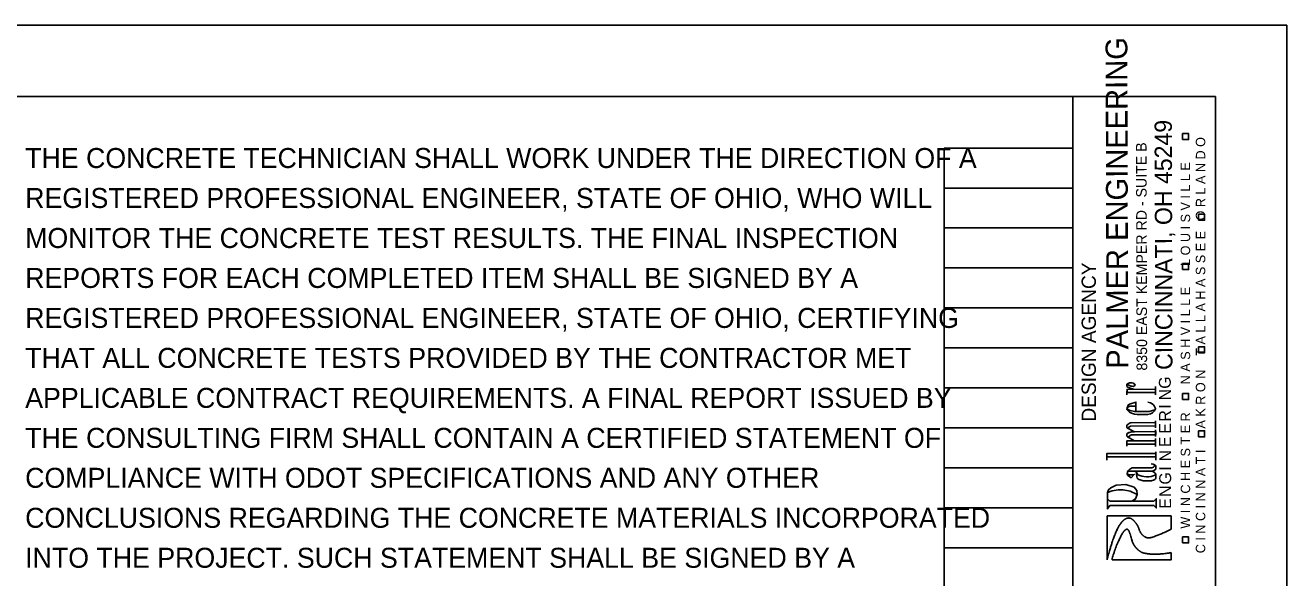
# Model space of a CAD drawing. Extents: x -14.8 to 34, y 0 to 43.2.
# Drawn here: x 25.16 to 34, y 18.13 to 22 of the extents above; entities that cross this region are included whole.
import ezdxf

# ---------------------------------------------------------------- set-up
doc = ezdxf.new("R2010")
doc.units = 0
for name, color, linetype in [('SH_Border', 7, 'Continuous'), ('SH_Cut_Line', 7, 'Continuous'), ('SH_Data', 7, 'Continuous'), ('SH_Text', 7, 'Continuous')]:
    doc.layers.add(name, color=color, linetype=linetype)

msp = doc.modelspace()

# ---------------------------------------------------------------- linework, layer by layer
at = {"layer": 'SH_Border'}
msp.add_line((32.5, 0.5), (32.5, 21.5), dxfattribs=at)
msp.add_lwpolyline([(2, 21.5), (33.5, 21.5), (33.5, 0.5), (2, 0.5)], close=True, dxfattribs=at)
at = {"layer": 'SH_Cut_Line'}
msp.add_lwpolyline([(0, 22), (34, 22), (34, 0), (0, 0)], close=True, dxfattribs=at)
at = {"layer": 'SH_Data'}
for p, q in [((31.6, 0.98), (31.6, 21.14)), ((31.6, 21.14), (32.5, 21.14)), ((32.5, 0.98), (32.5, 21.14)), ((31.6, 20.86), (32.5, 20.86)), ((31.6, 20.58), (32.5, 20.58)), ((31.6, 20.3), (32.5, 20.3)), ((31.6, 20.02), (32.5, 20.02)), ((31.6, 19.74), (32.5, 19.74)), ((32.9208, 19.773), (32.9208, 19.773)), ((33.2542, 19.7731), (33.2542, 19.7731)), ((31.6, 19.46), (32.5, 19.46)), ((31.6, 19.18), (32.5, 19.18)), ((31.6, 18.9), (32.5, 18.9)), ((31.6, 18.62), (32.5, 18.62)), ((31.6, 18.34), (32.5, 18.34))]:
    msp.add_line(p, q, dxfattribs=at)
at = {"layer": 'SH_Text'}
for p, q in [((32.741, 18.5628), (32.741, 18.2567)), ((33.1908, 18.5628), (32.741, 18.5628)), ((33.1908, 18.47), (33.1908, 18.5628)), ((32.741, 18.2567), (32.741, 18.2567)), ((32.7758, 18.2567), (32.7758, 18.2567))]:
    msp.add_line(p, q, dxfattribs=at)
for points in [[(33.2695, 21.1988), (33.3123, 21.1988), (33.3123, 21.2417), (33.2704, 21.2408)], [(33.3808, 20.6337), (33.4236, 20.6337), (33.4236, 20.6765), (33.3817, 20.6756)], [(33.2695, 20.2887), (33.3123, 20.2887), (33.3123, 20.3316), (33.2704, 20.3307)], [(33.3808, 19.7055), (33.4236, 19.7055), (33.4236, 19.7484), (33.3817, 19.7475)], [(32.8803, 19.4854), (32.8981, 19.4952), (32.916, 19.4952), (32.9249, 19.4934), (32.9383, 19.48), (32.9383, 19.4782), (32.9249, 19.4702), (32.916, 19.4711), (32.907, 19.4729)], [(32.8803, 19.4274), (32.8812, 19.4497), (33.0802, 19.4506), (33.0802, 19.4283)], [(32.9427, 19.331), (32.9026, 19.331), (32.8874, 19.3274), (32.8829, 19.3229), (32.8829, 19.3203), (32.882, 19.3158), (32.8838, 19.3113), (32.8856, 19.3087), (32.9026, 19.3015), (32.9338, 19.2944), (33.0355, 19.2944), (33.0766, 19.3069), (33.0721, 19.2988), (33.0587, 19.2855), (33.0463, 19.2792), (33.0275, 19.2739), (32.9517, 19.2739), (32.9338, 19.2765), (32.9115, 19.2819), (32.899, 19.289), (32.8803, 19.3087), (32.8812, 19.3212), (32.8892, 19.339), (32.8981, 19.3461), (32.9427, 19.3604)], [(33.2695, 19.3783), (33.3123, 19.3783), (33.3123, 19.4211), (33.2704, 19.4202)], [(32.8883, 19.1757), (32.882, 19.181), (32.8794, 19.1828), (32.8794, 19.198), (32.8883, 19.206), (32.9026, 19.2141), (32.9106, 19.2159), (33.0811, 19.2167), (33.0811, 19.1944), (32.9061, 19.1918), (32.8972, 19.1882), (32.8936, 19.1855)], [(32.8883, 19.1141), (32.8847, 19.1177), (32.8794, 19.1221), (32.8794, 19.1373), (32.891, 19.1462), (32.9115, 19.1525), (32.9329, 19.1525), (33.082, 19.1534), (33.082, 19.1302), (32.9115, 19.1302), (32.9017, 19.1266)], [(33.3808, 19.1164), (33.4236, 19.1164), (33.4236, 19.1592), (33.3817, 19.1583)], [(32.8803, 19.0659), (32.8803, 19.0882), (33.0811, 19.0891), (33.0811, 19.0659)], [(32.7384, 18.9776), (32.7384, 18.9999), (33.082, 18.9999), (33.082, 18.9767)], [(33.0507, 18.9285), (33.0641, 18.9258), (33.073, 18.9204), (33.073, 18.9124), (33.0659, 18.9044), (33.0552, 18.8999), (32.9177, 18.8999), (32.8999, 18.891), (32.8954, 18.887), (32.8927, 18.8847), (32.8829, 18.8714), (32.882, 18.8571), (32.8874, 18.8473), (32.8919, 18.8428), (32.9088, 18.8303), (32.9311, 18.8535), (32.9222, 18.8508), (32.8954, 18.8499), (32.8874, 18.8535), (32.8838, 18.8598), (32.8838, 18.8705), (32.887, 18.8772), (32.8865, 18.8767), (33.0596, 18.8767), (33.0766, 18.866), (33.082, 18.8571), (33.0757, 18.8482), (33.0641, 18.8428), (33.0489, 18.8383), (33.0329, 18.8366), (33.0177, 18.8366), (32.999, 18.8383), (32.9838, 18.841), (32.9704, 18.8455), (32.9637, 18.8486), (32.957, 18.8517), (32.9508, 18.8589), (32.9445, 18.8767), (32.949, 18.8374), (32.9517, 18.8285), (32.9561, 18.8241), (32.9641, 18.8187), (32.9717, 18.816), (32.9793, 18.8134), (32.9865, 18.8116), (32.9936, 18.8098), (33.0012, 18.8089), (33.0088, 18.808), (33.048, 18.808), (33.0529, 18.8098), (33.0579, 18.8116), (33.0659, 18.8134), (33.0748, 18.8187), (33.0802, 18.8232), (33.082, 18.8285), (33.082, 18.8571), (33.0766, 18.866), (33.0596, 18.8767), (33.073, 18.883), (33.082, 18.891), (33.082, 18.9142), (33.073, 18.9204), (33.0641, 18.9258)], [(32.7428, 18.6839), (32.7428, 18.6125), (32.7607, 18.6366), (33.0686, 18.6366), (33.0855, 18.6197), (33.0855, 18.6839), (33.0677, 18.667), (32.9213, 18.667), (32.9392, 18.6822), (32.9517, 18.7143), (32.9499, 18.742), (32.9302, 18.7643), (32.8722, 18.7839), (32.8053, 18.7785), (32.7678, 18.7607), (32.7517, 18.7464), (32.7428, 18.7268), (32.7758, 18.7393), (32.8187, 18.7455), (32.8535, 18.7464), (32.9035, 18.7375), (32.9517, 18.7143), (32.9392, 18.6822), (32.9151, 18.667), (32.7607, 18.667), (32.7428, 18.6839), (32.7428, 18.7268)], [(33.2695, 18.3737), (33.3123, 18.3737), (33.3123, 18.4166), (33.2704, 18.4157)]]:
    msp.add_lwpolyline(points, close=True, dxfattribs=at)
for points in [[(32.9249, 19.4506), (32.9026, 19.4586), (32.8856, 19.4657), (32.8803, 19.4702), (32.8803, 19.4854), (32.8981, 19.4952), (32.916, 19.4952), (32.9249, 19.4934), (32.9338, 19.4854), (32.9383, 19.48), (32.9383, 19.4782), (32.9249, 19.4702), (32.916, 19.4711), (32.907, 19.4729), (32.8803, 19.4854)], [(32.8803, 19.4104), (32.8812, 19.4497), (33.0802, 19.4506)], [(33.0802, 19.4104), (33.0802, 19.4702)], [(32.9427, 19.2935), (32.9427, 19.3604), (32.8981, 19.3461), (32.8892, 19.339), (32.8847, 19.3256), (32.8812, 19.3212), (32.8803, 19.3087), (32.899, 19.289), (32.9115, 19.2819), (32.9338, 19.2765), (32.9517, 19.2739), (33.0275, 19.2739), (33.0463, 19.2792), (33.0587, 19.2855), (33.0721, 19.2988), (33.0811, 19.3167), (33.0766, 19.3256), (33.0712, 19.3337), (33.0632, 19.3444), (33.0454, 19.356), (33.0275, 19.3604)], [(32.9427, 19.331), (32.9026, 19.331), (32.8901, 19.3283), (32.8847, 19.3256)], [(32.9338, 19.0882), (32.8847, 19.1177), (32.8794, 19.1221), (32.8794, 19.1373), (32.8883, 19.1445), (32.8936, 19.148), (32.9115, 19.1525), (32.9329, 19.1525), (32.8847, 19.1784), (32.8794, 19.1828), (32.8794, 19.198), (32.8883, 19.206), (32.9026, 19.2141), (32.9106, 19.2159), (33.0811, 19.2167)], [(33.0811, 19.181), (33.0811, 19.2301)], [(33.0811, 19.1195), (33.0811, 19.165)], [(33.0811, 19.0499), (33.0811, 19.1043)], [(32.8803, 19.0507), (32.8803, 19.0882), (33.0811, 19.0891)], [(33.082, 18.9544), (33.082, 19.0115)], [(32.7384, 18.9526), (32.7384, 18.9999), (33.082, 18.9999)], [(32.7758, 18.2567), (33.1908, 18.2567), (33.1908, 18.3058)]]:
    msp.add_lwpolyline(points, dxfattribs=at)
for centre, major_axis, ratio, start_param, end_param in [((33.2642, 18.3025), (-0.4905, 0), 0.87846, 5.855193, 5.894118), ((33.0097, 18.4045), (-0.2108, 0), 0.87846, 5.795806, 5.855193), ((33.0658, 18.3784), (-0.2743, 0), 0.87846, 5.749826, 5.795806), ((33.1077, 18.3566), (-0.3229, 0), 0.87846, 5.707452, 5.749826), ((33.2256, 18.2894), (-0.4635, 0), 0.87846, 5.692164, 5.707452), ((32.8595, 18.5052), (-0.0226, 0), 0.87846, 5.62293, 5.692164), ((32.86, 18.5049), (-0.0233, 0), 0.87846, 5.530169, 5.62293), ((32.8297, 18.5301), (-0.0186, 0), 0.87846, 2.376805, 2.493109), ((32.7929, 18.5546), (-0.0647, 0), 0.87846, 2.493108, 2.531888), ((32.8891, 18.4958), (-0.0525, 0), 0.87846, 5.630169, 5.678013), ((32.9316, 18.4673), (-0.106, 0), 0.87846, 5.621033, 5.63017), ((33.5343, 18.0545), (-0.8702, 0), 0.87846, 5.617844, 5.621032), ((32.9292, 18.4716), (-0.101, 0), 0.87846, 5.581326, 5.617844), ((32.958, 18.4503), (-0.1387, 0), 0.87846, 5.55016, 5.581326), ((32.8723, 18.518), (-0.0234, 0), 0.87846, 5.403561, 5.55016), ((32.9933, 18.3895), (-0.2133, 0), 0.87846, 5.35501, 5.403561), ((32.9271, 18.4673), (-0.1027, 0), 0.87846, 5.295141, 5.35501), ((32.9077, 18.4931), (-0.0675, 0), 0.87846, 5.221294, 5.295141), ((32.8871, 18.5255), (-0.0253, 0), 0.87846, 5.021813, 5.221294), ((32.8954, 18.5027), (-0.0525, 0), 0.87846, 4.883334, 5.021813), ((32.8945, 18.5076), (-0.0469, 0), 0.87846, 4.755052, 4.883334), ((32.8934, 18.5286), (-0.023, 0), 0.87846, 4.571575, 4.755052), ((32.8907, 18.5115), (-0.0426, 0), 0.87846, 4.449144, 4.571575), ((32.8967, 18.531), (-0.0196, 0), 0.87846, 4.268543, 4.449144), ((32.8633, 18.4693), (-0.0974, 0), 0.87846, 4.241427, 4.268543), ((32.8979, 18.5291), (-0.021, 0), 0.87846, 4.183087, 4.241427), ((32.8758, 18.4959), (-0.0647, 0), 0.87846, 4.138734, 4.183087), ((32.8855, 18.5091), (-0.0469, 0), 0.87846, 4.086609, 4.138734), ((32.8832, 18.5062), (-0.0509, 0), 0.87846, 4.024354, 4.086609), ((32.8849, 18.5081), (-0.0481, 0), 0.87846, 3.960321, 4.024354), ((32.8482, 18.4737), (-0.1019, 0), 0.87846, 3.920059, 3.960321), ((32.7808, 18.4153), (-0.1965, 0), 0.87846, 3.891072, 3.920059), ((32.6774, 18.3307), (-0.3379, 0), 0.87846, 3.874263, 3.891072), ((32.8217, 18.4447), (-0.1437, 0), 0.87846, 3.848492, 3.874263), ((32.8307, 18.4515), (-0.1318, 0), 0.87846, 3.81119, 3.848492), ((32.7814, 18.4172), (-0.1947, 0), 0.87846, 3.780496, 3.811191), ((32.7693, 18.4094), (-0.2098, 0), 0.87846, 3.754086, 3.780496), ((32.8146, 18.4373), (-0.1544, 0), 0.87846, 3.723306, 3.754086), ((32.7885, 18.4222), (-0.1857, 0), 0.87846, 3.696658, 3.723306), ((32.8051, 18.4313), (-0.1662, 0), 0.87846, 3.66849, 3.696658), ((32.78, 18.4184), (-0.1952, 0), 0.87846, 3.643808, 3.66849), ((32.8348, 18.4449), (-0.1326, 0), 0.87846, 3.613866, 3.643809), ((32.8635, 18.4578), (-0.1004, 0), 0.87846, 3.588674, 3.613866), ((32.7958, 18.4292), (-0.1755, 0), 0.87846, 3.569621, 3.588674), ((32.847, 18.4498), (-0.1192, 0), 0.87846, 3.522125, 3.569621), ((32.7863, 18.4284), (-0.1846, 0), 0.87846, 3.483955, 3.522125), ((32.8049, 18.4342), (-0.1649, 0), 0.87846, 3.442005, 3.483955), ((33.33, 18.5772), (-0.3849, 0), 0.87846, 0.300413, 0.327872), ((33.2036, 18.2843), (-0.4404, 0), 0.87846, 5.967993, 6.015499), ((34.0259, 18.0488), (-1.3053, 0), 0.87846, 5.940399, 5.967993), ((33.5753, 18.1901), (-0.8269, 0), 0.87846, 5.917138, 5.940399), ((33.5917, 18.1846), (-0.8444, 0), 0.87846, 5.894118, 5.917138), ((32.3944, 18.5495), (-0.4655, 0), 0.87846, 2.717844, 2.740099), ((32.0455, 18.6796), (-0.8445, 0), 0.87846, 2.740099, 2.758854), ((33.8353, 18.0445), (-1.0858, 0), 0.87846, 5.883775, 5.898363), ((33.3213, 18.2351), (-0.5279, 0), 0.87846, 5.860363, 5.883775), ((33.5257, 18.1543), (-0.752, 0), 0.87846, 5.840747, 5.860363), ((33.0115, 18.3683), (-0.183, 0), 0.87846, 5.783384, 5.840747), ((32.9209, 18.4117), (-0.0798, 0), 0.87846, 5.696475, 5.783384), ((32.9155, 18.4149), (-0.0732, 0), 0.87846, 5.643254, 5.696475), ((32.9804, 18.3725), (-0.1542, 0), 0.87846, 5.60658, 5.643254), ((32.9543, 18.3909), (-0.1206, 0), 0.87846, 5.557186, 5.60658), ((32.8887, 18.4421), (-0.0329, 0), 0.87846, 5.462631, 5.557186), ((32.8786, 18.4516), (-0.0181, 0), 0.87846, 5.357779, 5.462631), ((32.9369, 18.3836), (-0.115, 0), 0.87846, 5.31618, 5.357779), ((32.9007, 18.4297), (-0.0513, 0), 0.87846, 5.228087, 5.31618), ((32.8836, 18.4561), (-0.0167, 0), 0.87846, 5.073461, 5.228087), ((32.8804, 18.4635), (-0.0077, 0), 0.87846, 4.821391, 5.073461), ((32.8804, 18.4637), (-0.00751, 0), 0.87846, 4.566078, 4.821391), ((32.88, 18.4612), (-0.0104, 0), 0.87846, 4.422741, 4.566078), ((32.8814, 18.4655), (-0.00528, 0), 0.87846, 4.221707, 4.422741), ((32.8792, 18.4618), (-0.01, 0), 0.87846, 4.079149, 4.221707), ((32.879, 18.4616), (-0.0103, 0), 0.87846, 3.938698, 4.079149), ((32.8714, 18.4547), (-0.0212, 0), 0.87846, 3.832303, 3.938698), ((32.8569, 18.4442), (-0.0401, 0), 0.87846, 3.754926, 3.832303), ((32.8493, 18.4395), (-0.0493, 0), 0.87846, 3.694946, 3.754926), ((32.8599, 18.4452), (-0.0369, 0), 0.87846, 3.625598, 3.694946), ((32.8497, 18.4405), (-0.0484, 0), 0.87846, 3.510006, 3.625598), ((32.7931, 18.4213), (-0.109, 0), 0.87846, 3.433025, 3.510006), ((32.3633, 18.3081), (-0.5578, 0), 0.87846, 3.419929, 3.433025), ((32.3942, 18.3158), (-0.5256, 0), 0.87846, 3.406439, 3.419929), ((32.3264, 18.2997), (-0.5959, 0), 0.87846, 3.372647, 3.406439), ((33.5984, 18.5643), (-0.7113, 0), 0.87846, 0.233797, 0.262104), ((33.5275, 18.5476), (-0.6379, 0), 0.87846, 0.262104, 0.288235), ((33.1839, 18.4581), (-0.2794, 0), 0.87846, 0.288235, 0.327718), ((33.4252, 18.6056), (-0.4854, 0), 0.87846, 0.327872, 0.349116), ((33.2147, 18.5383), (-0.2614, 0), 0.87846, 0.349116, 0.378064), ((33.0421, 18.4781), (-0.0757, 0), 0.87846, 0.378064, 0.470832), ((33.0561, 18.4843), (-0.0914, 0), 0.87846, 0.470832, 0.55527), ((33.0797, 18.4972), (-0.1192, 0), 0.87846, 0.55527, 0.595966), ((33.048, 18.4783), (-0.0808, 0), 0.87846, 0.595966, 0.645395), ((33.0846, 18.5025), (-0.1267, 0), 0.87846, 0.645395, 0.693591), ((33.0652, 18.4884), (-0.1015, 0), 0.87846, 0.693591, 0.747442), ((33.0677, 18.4904), (-0.1049, 0), 0.87846, 0.747442, 0.78677), ((33.0555, 18.4796), (-0.0875, 0), 0.87846, 0.78677, 0.829814), ((33.0413, 18.466), (-0.0665, 0), 0.87846, 0.829814, 0.891343), ((33.0615, 18.488), (-0.0987, 0), 0.87846, 0.891343, 0.941835), ((33.0381, 18.4597), (-0.0588, 0), 0.87846, 0.941835, 1.007249), ((33.0381, 18.4597), (-0.059, 0), 0.87846, 1.007249, 1.072591), ((33.0285, 18.4443), (-0.0389, 0), 0.87846, 1.072591, 1.167276), ((33.0353, 18.4582), (-0.0561, 0), 0.87846, 1.167276, 1.246088), ((33.0298, 18.4438), (-0.0388, 0), 0.87846, 1.246088, 1.327189), ((33.0398, 18.4791), (-0.0803, 0), 0.87846, 1.327189, 1.383552), ((33.0332, 18.4484), (-0.0447, 0), 0.87846, 1.383552, 1.501127), ((33.033, 18.4461), (-0.0421, 0), 0.87846, 1.501127, 1.622304), ((33.0334, 18.4395), (-0.0345, 0), 0.87846, 1.622304, 1.749821), ((33.0227, 18.4913), (-0.0945, 0), 0.87846, 1.749821, 1.826883), ((33.0038, 18.5547), (-0.169, 0), 0.87846, 1.826883, 1.911738), ((32.9737, 18.6292), (-0.259, 0), 0.87846, 1.911738, 1.980277), ((32.9885, 18.5993), (-0.222, 0), 0.87846, 1.980277, 2.010465), ((26.2419, 31.1989), (-16.0723, 0), 0.87846, 2.010465, 2.014013), ((32.8734, 18.9275), (-0.6089, 0), 0.87846, 2.014013, 2.046232), ((32.1383, 20.1818), (-2.2149, 0), 0.87846, 2.046232, 2.065925), ((89.7981, 4.5961), (-59.1554, 0), 0.875342, 6.014819, 6.015491), ((24.8437, 20.2387), (-8.2103, 0), 0.87846, 2.873226, 2.875028), ((22.059, 20.9067), (-11.097, 0), 0.87846, 2.875028, 2.877571), ((38.4652, 17.0166), (-5.8963, 0), 0.87846, 6.015499, 6.020286), ((33.2381, 18.189), (-0.4679, 0), 0.87846, 5.989667, 6.035373), ((51.827, 13.2534), (-19.8873, 0), 0.87846, 5.987304, 5.989667), ((32.8817, 18.3265), (-0.0813, 0), 0.87846, 5.950356, 5.987304), ((33.5218, 18.1321), (-0.7587, 0), 0.87846, 5.926295, 5.950356), ((33.0174, 18.2974), (-0.2203, 0), 0.87846, 5.881639, 5.926295), ((33.2451, 18.2124), (-0.4677, 0), 0.87846, 5.859489, 5.881639), ((33.0618, 18.4217), (-0.1505, 0), 0.87846, 0.327717, 0.369872), ((33.1254, 18.4433), (-0.2187, 0), 0.87846, 0.369872, 0.404843), ((33.0756, 18.4246), (-0.1645, 0), 0.87846, 0.404843, 0.455087), ((32.9457, 18.3687), (-0.02, 0), 0.87846, 0.455087, 0.599404), ((33.2784, 18.5684), (-0.4228, 0), 0.87846, 0.599404, 0.60619), ((32.0083, 17.7974), (-1.121, 0), 0.87846, 3.743109, 3.745669), ((31.3225, 17.384), (-1.9527, 0), 0.87846, 3.737876, 3.743109), ((33.4293, 18.6363), (-0.5911, 0), 0.87846, 0.590254, 0.607546), ((32.9752, 18.3589), (-0.038, 0), 0.87846, 0.607546, 0.683488), ((33.2416, 18.5495), (-0.3816, 0), 0.87846, 0.683488, 0.707435), ((33.1194, 18.4577), (-0.2207, 0), 0.87846, 0.707435, 0.74169), ((33.03, 18.3857), (-0.0995, 0), 0.87846, 0.74169, 0.792719), ((33.0001, 18.3591), (-0.0569, 0), 0.87846, 0.792719, 0.856881), ((33.0633, 18.4232), (-0.1535, 0), 0.87846, 0.856881, 0.895951), ((33.0359, 18.3931), (-0.1096, 0), 0.87846, 0.895951, 0.952796), ((33.0547, 18.4164), (-0.1421, 0), 0.87846, 0.952796, 1.002719), ((33.0125, 18.3583), (-0.0636, 0), 0.87846, 1.002719, 1.074215), ((33.0336, 18.3925), (-0.1079, 0), 0.87846, 1.074215, 1.129118), ((33.0143, 18.3566), (-0.0627, 0), 0.87846, 1.129118, 1.249501), ((33.0482, 18.4461), (-0.1701, 0), 0.87846, 1.249501, 1.322556), ((33.054, 18.4662), (-0.1937, 0), 0.87846, 1.322556, 1.389057), ((33.0529, 18.4608), (-0.1875, 0), 0.87846, 1.389057, 1.456641), ((32.0826, 25.329), (-8.0725, 0), 0.87846, 1.701726, 1.704171), ((33.1099, 18.6034), (-0.3478, 0), 0.87846, 1.704171, 1.737317), ((33.008, 19.136), (-0.9625, 0), 0.87846, 1.737317, 1.761789), ((33.9666, 18.0488), (-1.2485, 0), 0.87846, 6.068704, 6.092552), ((32.973, 18.2389), (-0.2316, 0), 0.87846, 6.015491, 6.068704), ((34.1849, 17.9785), (-1.4445, 0), 0.87846, 6.035373, 6.06218), ((33.056, 18.4849), (-0.2151, 0), 0.87846, 1.456641, 1.513412), ((33.075, 18.7758), (-0.5468, 0), 0.87846, 1.513412, 1.549016), ((33.0781, 18.9005), (-0.6888, 0), 0.87846, 1.549016, 1.607781), ((33.0908, 18.599), (-0.3453, 0), 0.87846, 1.607781, 1.690785), ((33.0839, 18.6493), (-0.403, 0), 0.87846, 1.690785, 1.701726)]:
    msp.add_ellipse(centre, major_axis=major_axis, ratio=ratio, start_param=start_param, end_param=end_param, dxfattribs=at)

# ---------------------------------------------------------------- texts
at = {"layer": 'SH_Data'}
msp.add_text('DESIGN AGENCY', height=0.1, rotation=90, dxfattribs=at).set_placement((32.6625, 19.2237))
at = {"layer": 'SH_Text'}
for s, height, rotation, p in [('PALMER ENGINEERING', 0.15245, 90.15796, (32.8892, 19.5946)), ('CINCINNATI, OH 45249', 0.12089, 90.15796, (33.1994, 19.5857)), ('8350 EAST KEMPER RD - SUITE B', 0.074183, 90.15796, (33.0218, 19.5811)), ('C I N C I N N A T I      A K R O N    T A L L A H A S S E E   O R L A N D O', 0.066042, 90, (33.4288, 18.3017)), ('W I N C H E S T E R        N A S H V I L L E      L O U I S V I L L E', 0.066042, 90, (33.3229, 18.4743)), ('G', 0.0831, 90.12233, (33.1873, 19.4541)), ('N', 0.0831, 90.12233, (33.1882, 19.3728)), ('I', 0.0831, 90.12233, (33.1873, 19.3139)), ('R', 0.0831, 90.12233, (33.1882, 19.2238)), ('E', 0.0831, 90.12233, (33.189, 19.139)), ('E', 0.0831, 90.12233, (33.1882, 19.0453)), ('N', 0.0831, 90.12233, (33.1899, 18.9454)), ('G', 0.0831, 90.12233, (33.1899, 18.7829)), ('I', 0.0831, 90.12233, (33.189, 18.8802)), ('N', 0.0831, 90.12233, (33.1899, 18.6964)), ('E', 0.0831, 90.12233, (33.1899, 18.6134))]:
    msp.add_text(s, height=height, rotation=rotation, dxfattribs=at).set_placement(p)
for s, p in [('THE CONCRETE TECHNICIAN SHALL WORK UNDER THE DIRECTION OF A ', (25.16, 21)), ('REGISTERED PROFESSIONAL ENGINEER, STATE OF OHIO, WHO WILL ', (25.16, 20.72)), ('MONITOR THE CONCRETE TEST RESULTS. THE FINAL INSPECTION ', (25.16, 20.44)), ('REPORTS FOR EACH COMPLETED ITEM SHALL BE SIGNED BY A ', (25.16, 20.16)), ('REGISTERED PROFESSIONAL ENGINEER, STATE OF OHIO, CERTIFYING ', (25.16, 19.88)), ('THAT ALL CONCRETE TESTS PROVIDED BY THE CONTRACTOR MET ', (25.16, 19.6)), ('APPLICABLE CONTRACT REQUIREMENTS. A FINAL REPORT ISSUED BY ', (25.16, 19.32)), ('THE CONSULTING FIRM SHALL CONTAIN A CERTIFIED STATEMENT OF ', (25.16, 19.04)), ('COMPLIANCE WITH ODOT SPECIFICATIONS AND ANY OTHER ', (25.16, 18.76)), ('CONCLUSIONS REGARDING THE CONCRETE MATERIALS INCORPORATED ', (25.16, 18.48)), ('INTO THE PROJECT. SUCH STATEMENT SHALL BE SIGNED BY A ', (25.16, 18.2))]:
    msp.add_text(s, height=0.14, dxfattribs=at).set_placement(p)

doc.saveas('drawing.dxf')
